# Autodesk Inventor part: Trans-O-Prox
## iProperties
Shininess: 64.0
Length Units: 11269
Angle Units: 11279
Time Units: 11290
Mass Units: 11283
Length Display Precision: 3
Angle Display Precision: 2
Compacted: True
Part Number: Trans-O-Prox
Document SubType Name: Modeling
Created: 2005-07
Material: Kunststoffgehäuse
Designer: Tanck
Manufacturer: Standard
Standards Organization: Custom
Density: 0.0
Volumn: 0.0
Area: 0.0
PropertySet Name: Model Information
Control State: 0
Master: False
Checked Out: False
Last Check In By: Tanck
Last Check In Date: 2005-08-11
Author: Tanck
Title: microsonic
Subject: Nachschaltgerät
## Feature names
1. Grundkörper [Extrusion]
2. Schalthaube [Extrusion]
3. Profilkontur [Extrusion]
4. Klemmenaussparung oben [Extrusion]
5. Klemmenaussparung mitten [Extrusion]
6. Klemmenaussparung unten [Extrusion]
7. Klemmenschlitz [Extrusion]
8. Klemmenaussparungen unten [Mirror]
9. Klemmenaussparungen [Rectangular Pattern]
10. Bodenprofil [Extrusion]
11. Bodenprofil mittig [Extrusion]
12. Vertikale Nut [Extrusion]
13. Nutenstein unten [Extrusion]
14. Nutenstein oben [Extrusion]
15. Nutensteinkehlung [Extrusion]
16. Fase Nutenstein vorn [Chamfer]
17. Versteifung rechts [Extrusion]
18. Versteifung links [Mirror]
19. Versteifung [Fillet]
20. Bohrung oben [Extrusion]
21. Bohrungen oben [Rectangular Pattern]
22. Bohrung unten [Extrusion]
23. Bohrungen unten [Rectangular Pattern]
24. Schraubenkopf oben [Extrusion]
25. Rundung Schraubenkopf oben [Fillet]
26. Schraubenschlitz oben [Extrusion]
27. Kreuzschlitz oben [Extrusion]
28. Schrauben oben [Rectangular Pattern]
29. Schraubenkopf unten [Extrusion]
30. Rundung Schraubenkopf unten [Fillet]
31. Schraubenschlitz unten [Extrusion]
32. Kreuzschlitz unten [Extrusion]
33. Schrauben unten [Rectangular Pattern]
34. Bedienfeld Trans O Prox [Extrusion]
35. LED Trans O Prox [Revolution]
36. LED`s Trans O Prox [Rectangular Pattern]
37. Druckschalter [Revolution]
38. Druckschalter vertikal [Rectangular Pattern]
39. Serieller Anschluß [Extrusion]
40. Füllung Serieller Anschluß [Extrusion]
41. Rundung Serieller Anschluß [Fillet]
42. Bohrung1v5 [Extrusion]
43. 5 Bohrungen [Rectangular Pattern]
44. Bohrung1v4 [Extrusion]
45. 4 Bohrungen [Rectangular Pattern]
46. Fase Bohrungen [Chamfer]
47. Befestigungselemente [Extrusion]
48. Rundung Gewinde [Fillet]
49. Fase Gewinde [Chamfer]
50. Fase Befestigungselement unten [Revolution]
51. Fase Befestigungselement oben [Revolution]
52. Aussparung [Extrusion]
53. Aussparungen unten [Rectangular Pattern]
54. Aussparungen oben [Mirror]
55. Aussparung oben [Extrusion]
56. Aussparungen [Rectangular Pattern]
57. Schraube innen [Revolution]
58. Klemme innen [Extrusion]
59. Klemmen innen [Rectangular Pattern]
60. Schraube außen [Revolution]
61. Klemme außen [Extrusion]
62. Klemmen außen [Rectangular Pattern]
63. Deckel oben vorn [Extrusion]
64. Deckel seitlich vorn [Extrusion]
65. Halteband vorn
66. Deckel oben hinten [Extrusion]
67. Deckel seitlich hinten [Extrusion]
68. Halteband hinten
69. Deckel außen [Rectangular Pattern]
